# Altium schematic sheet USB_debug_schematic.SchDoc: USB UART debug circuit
size A3; Organization: Altium Limited; Address1: L3, 12a Rodborough Rd; Address2: Frenchs Forest; Address3: NSW; Address4: Australia 2086; DocumentNumber: 8; SheetNumber: 8; SheetTotal: 8
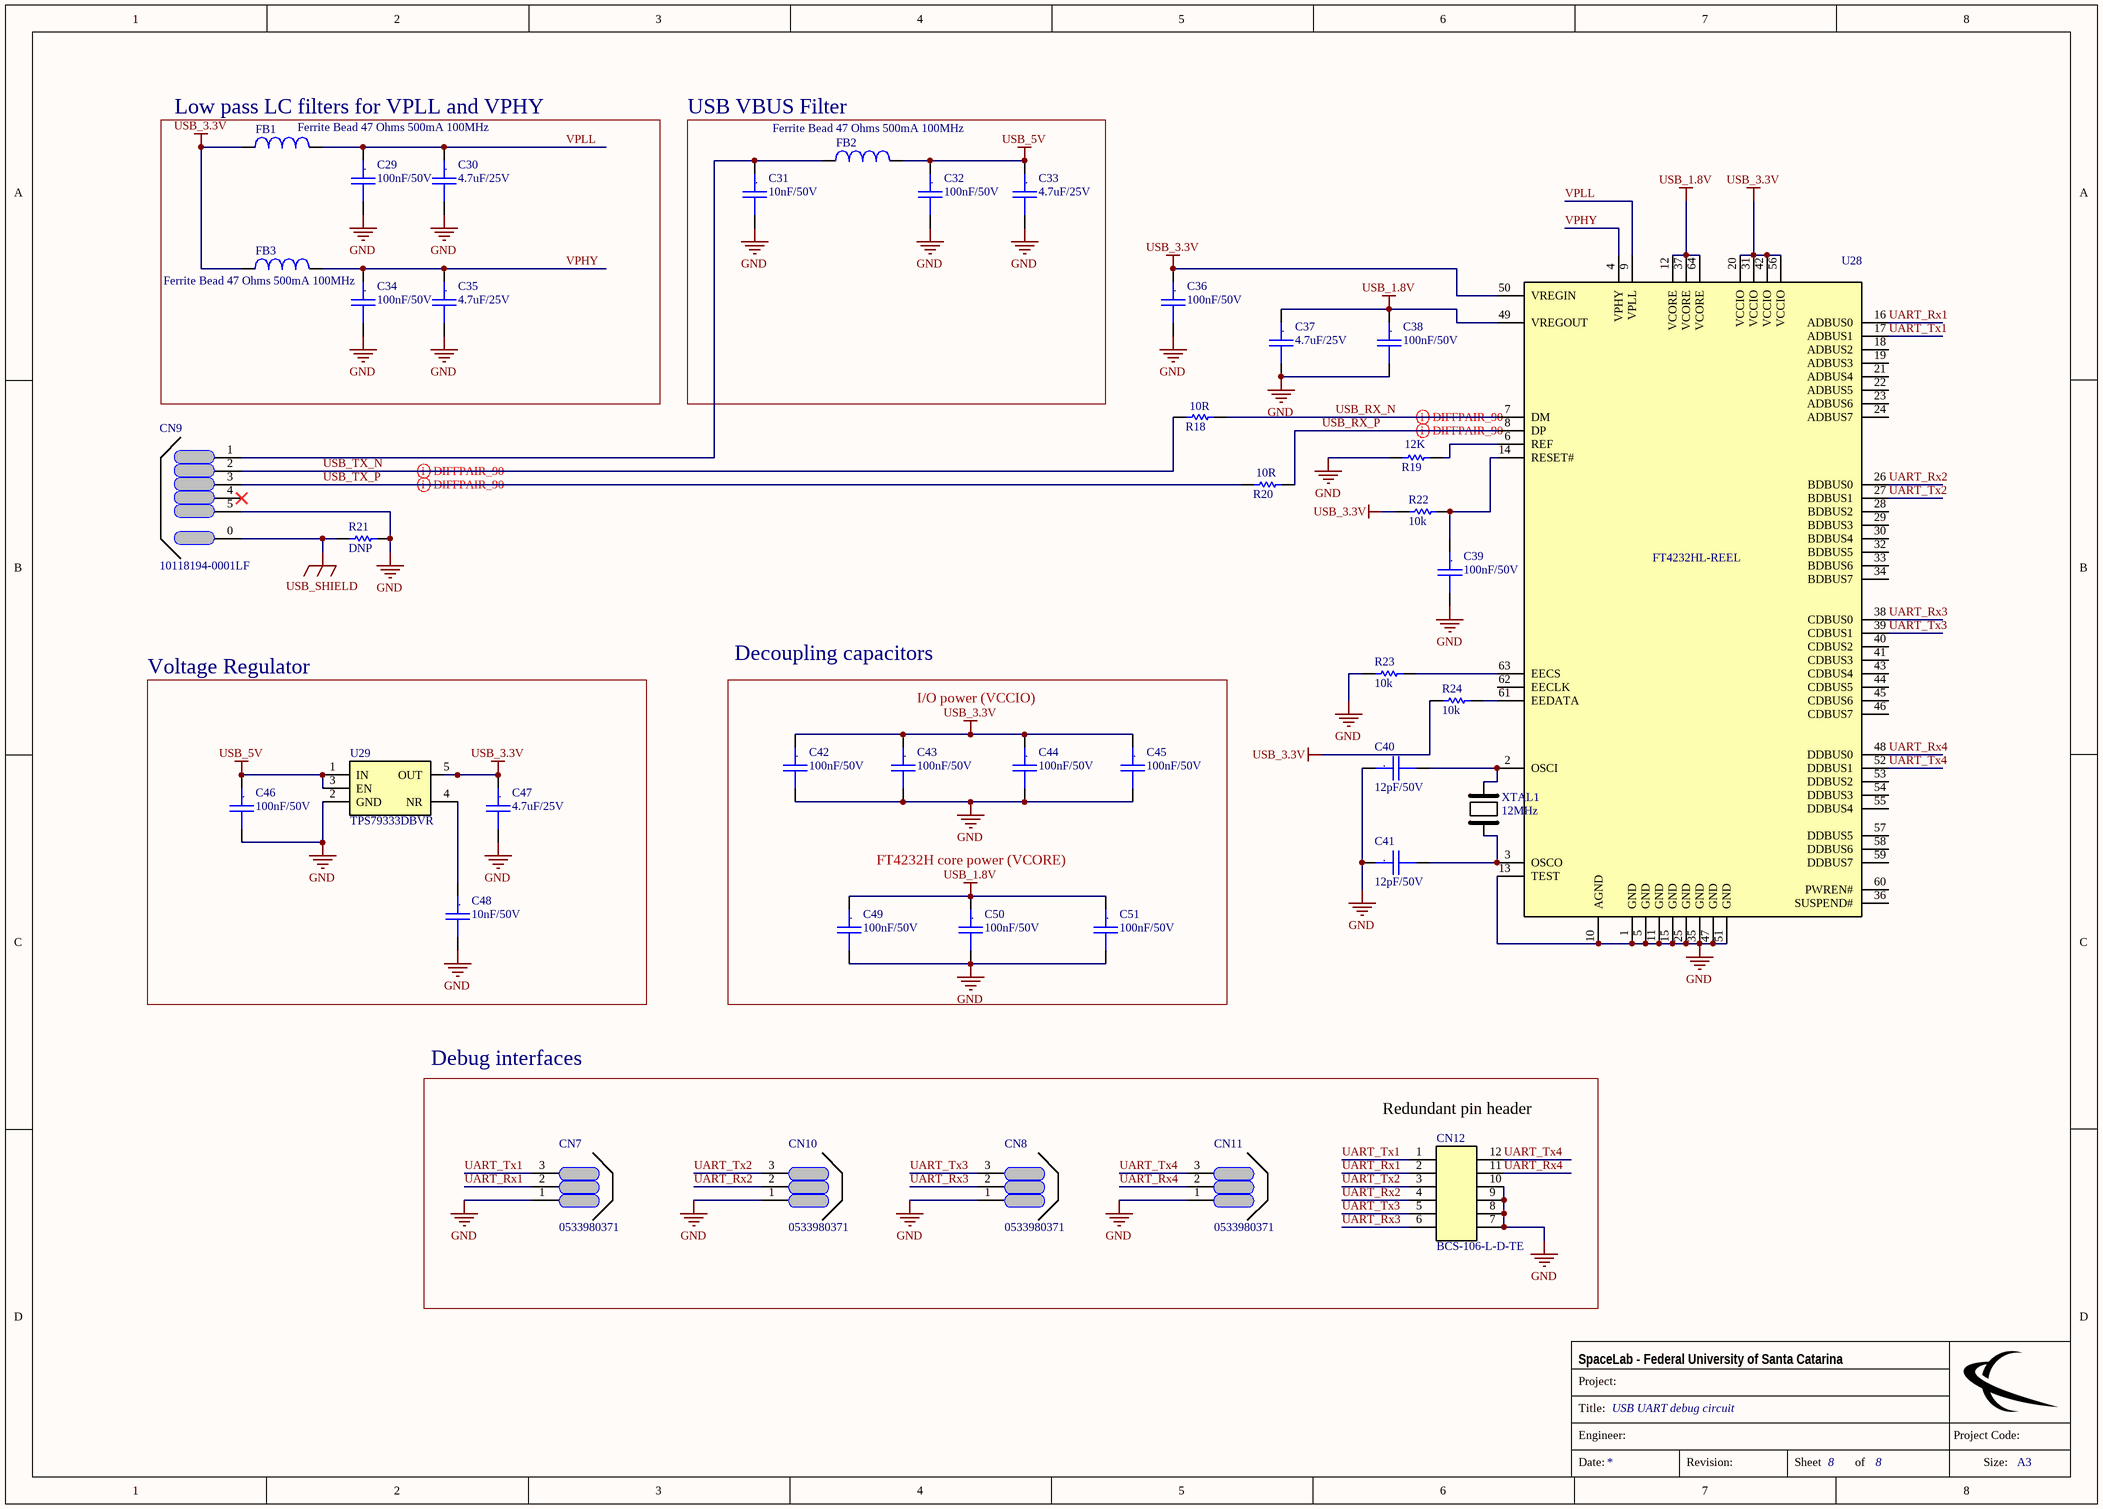
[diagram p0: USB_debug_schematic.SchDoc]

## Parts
C29  100nF/50V  [CC0603]
C30  4.7uF/25V  [CC0805]
C31  10nF/50V  [CC0805]
C32  100nF/50V  [CC0603]
C33  4.7uF/25V  [CC0805]
C34  100nF/50V  [CC0603]
C35  4.7uF/25V  [CC0805]
C36  100nF/50V  [CC0603]
C37  4.7uF/25V  [CC0805]
C38  100nF/50V  [CC0603]
C39  100nF/50V  [CC0603]
C40  12pF/50V  [CC0805]
C41  12pF/50V  [CC0805]
C42  100nF/50V  [CC0603]
C43  100nF/50V  [CC0603]
C44  100nF/50V  [CC0603]
C45  100nF/50V  [CC0603]
C46  100nF/50V  [CC0603]
C47  4.7uF/25V  [CC0805]
C48  10nF/50V  [CC0805]
C49  100nF/50V  [CC0603]
C50  100nF/50V  [CC0603]
C51  100nF/50V  [CC0603]
CN7  0533980371  [PICO BLADE 0533980371]
CN8  0533980371  [PICO BLADE 0533980371]
CN9  10118194-0001LF  [MICRO USB B 90GRAUS]
CN10  0533980371  [PICO BLADE 0533980371]
CN11  0533980371  [PICO BLADE 0533980371]
CN12  BCS-106-L-D-TE  [BCS-106-L-D-TE]
FB1  Ferrite Bead 47 Ohms 500mA 100MHz  [L0603]
FB2  Ferrite Bead 47 Ohms 500mA 100MHz  [L0603]
FB3  Ferrite Bead 47 Ohms 500mA 100MHz  [L0603]
R18  10R  [R0603_MD]
R19  12K  [R0805_MD]
R20  10R  [R0603_MD]
R21  DNP  [0805]
R22  10k  [0805]
R23  10k  [0805]
R24  10k  [0805]
U28  FT4232HL-REEL  [LQFP-64]
U29  TPS79333DBVR  [SOT23-5]
XTAL1  Frequency: 12MHz  [TXC 7A Series]  (hidden comment: 12.000MHz 12pF)

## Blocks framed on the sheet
Low pass LC filters for VPLL and VPHY: C29 C30 C34 C35 FB1 FB3
USB VBUS Filter: C31-C33 FB2
Voltage Regulator: C46-C48 U29
Decoupling capacitors: C42-C45 C49-C51
Debug interfaces: CN7 CN8 CN10-CN12

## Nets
GND: C29.2 C30.2 C31.2 C32.2 C33.2 C34.2 C35.2 C36.2 C37.2 C38.2 C39.2 C40.1 C41.1 C42.2 C43.2 C44.2 C45.2 C46.2 C47.2 C48.2 C49.2 C50.2 C51.2 CN7.1 CN8.1 CN9.5 CN10.1 CN11.1 CN12.7 CN12.8 CN12.9 CN12.10 R19.1 R21.1 R23.2 U28.1(GND) U28.5(GND) U28.10(AGND) U28.11(GND) U28.13(TEST) U28.15(GND) U28.25(GND) U28.35(GND) U28.47(GND) U28.51(GND) U29.2(GND)
USB_1.8V: C37.1 C38.1 C49.1 C50.1 C51.1 U28.12(VCORE) U28.37(VCORE) U28.49(VREGOUT) U28.64(VCORE)
USB_3.3V: C36.1 C42.1 C43.1 C44.1 C45.1 C47.1 FB1.1 FB3.1 R22.2 R24.2 U28.20(VCCIO) U28.31(VCCIO) U28.42(VCCIO) U28.50(VREGIN) U28.56(VCCIO) U29.5(OUT)
USB_5V: C32.1 C33.1 C46.1 FB2.2 U29.1(IN) U29.3(EN)
USB_SHIELD: CN9.0 R21.2
UART_Rx1: CN7.2 CN12.2 U28.16(ADBUS0)
UART_Rx2: CN10.2 CN12.4 U28.26(BDBUS0)
UART_Rx3: CN8.2 CN12.6 U28.38(CDBUS0)
UART_Rx4: CN11.2 CN12.11 U28.48(DDBUS0)
UART_Tx1: CN7.3 CN12.1 U28.17(ADBUS1)
UART_Tx2: CN10.3 CN12.3 U28.27(BDBUS1)
UART_Tx3: CN8.3 CN12.5 U28.39(CDBUS1)
UART_Tx4: CN11.3 CN12.12 U28.52(DDBUS1)
USB_RX_N: R18.2 U28.7(DM)
USB_RX_P: R20.2 U28.8(DP)
USB_TX_N: CN9.2 R18.1
USB_TX_P: CN9.3 R20.1
VPHY: C34.1 C35.1 FB3.2 U28.4(VPHY)
VPLL: C29.1 C30.1 FB1.2 U28.9(VPLL)
NetC31_1: C31.1 CN9.1 FB2.1
NetC39_1: C39.1 R22.1 U28.14(RESET#)
NetC40_2: C40.2 U28.2(OSCI) XTAL1.1
NetC41_2: C41.2 U28.3(OSCO) XTAL1.2
NetC48_1: C48.1 U29.4(NR)
NetR19_2: R19.2 U28.6(REF)
NetR23_1: R23.1 U28.63(EECS)
NetR24_1: R24.1 U28.61(EEDATA)

Not connected (* = marked no-connect by the designer): CN9 4*; U28 18(ADBUS2) 19(ADBUS3) 21(ADBUS4) 22(ADBUS5) 23(ADBUS6) 24(ADBUS7) 28(BDBUS2) 29(BDBUS3) 30(BDBUS4) 32(BDBUS5) 33(BDBUS6) 34(BDBUS7) 36(SUSPEND#) 40(CDBUS2) 41(CDBUS3) 43(CDBUS4) 44(CDBUS5) 45(CDBUS6) 46(CDBUS7) 53(DDBUS2) 54(DDBUS3) 55(DDBUS4) 57(DDBUS5) 58(DDBUS6) 59(DDBUS7) 60(PWREN#) 62(EECLK)

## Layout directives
differential pair: USB_RX_N, USB_RX_P, USB_TX_N, USB_TX_P

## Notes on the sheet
- I/O power (VCCIO)
- FT4232H core power (VCORE)
- (near CN12) Redundant pin header

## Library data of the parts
C29 C32 C34 C36 C38 C39 C42-C46 C49-C51 = Cap_Cer_X7R_100nF_50V_0603: CAP CER 100nF 50V 10% X7R 0603; Manufacturer Part Number: C0603C104K5RAC3121
C30 C33 C35 C37 C47 = Cap_Cer_X7R_4.7uF_25V_0805: CAP CER 4.7uF 25V 10% X7R 0805; Manufacturer Part Number: C0805C475K3RACAUTO
C31 C48 = Cap_Cer_X7R_10nF_50V_0805: CAP CER 0.01uF 50V 10% X7R 0805; Manufacturer Part Number: 08055C103KAT4A
C40 C41 = Cap_Cer_X7R_12pF_50V_0805: CAP CER 12pF 50V 1% C0G/NP0 0805; Manufacturer Part Number: CL21C120FBANNNC
CN7 CN8 CN10 CN11 = 0533980371: CONN HEADER SMD 3POS 1.25MM; Manufacturer: Molex; Manufacturer Part Number: 53398-0371; N of Positions: 3
CN9 = 10118194-0001LF: CONN USB MICRO B RECPT SMT R/A; Manufacturer: FCI; N of Positions: 5; Pitch: 0.65mm
CN12 = BCS-106-L-D-TE: CONN RCPT 12POS 0.1 GOLD PCB; Manufacturer: Samtec; Number of Contacts: 12; Gender: Receptacle; Max Current Rating: 5.9A; Contact Resistance: 10mR; Max Voltage Rating (AC): 475V; Pitch: 2.54mm; Row Spacing: 0.1inch
FB1-FB3 = 742792608: WURTH ELEKTRONIK   742792608   FERRITE BEAD, 47 OHM, 0.5A, 0603; Manufacturer: Wurth Electronics; Resistance: 100mR; Inductance: 1H; Tolerance: 25%; Number of Lines: 1
R18 R20 = RC0603FR-0710RL: RES 10R OHM 1/10W 1% 0603; Manufacturer: Yageo; Temperature Coefficient: 200ppm/°C; Voltage Rating (DC): 50V; Power Rating: 100mW
R19 = RMCF0805FT12K0: RES 12K OHM 1/8W 1% 0805; Manufacturer: Stackpole Electronics; Power Rating: 125mW; Temperature Coefficient: 100ppm/°C
R21 = RDNP_0805: RES DNP 0805; Manufacturer Part Number: CRCW08050000Z0EA
R22-R24 = R10k_1%_1/8W_0805: RES 10K OHM 1/8W 1%  0805; Manufacturer Part Number: CRCW080510K0FKEA
U28 = FT4232HL-REEL: FTDI - FT4232HL-REEL - USB-UART/MPSSE, 4232, QUAD, 64LQFP; Number of Channels: 1; Data Rate: 480Mbps; Operating Supply Voltage: 3.3V; Max Supply Voltage: 3.63V; Min Supply Voltage: 1.62V; Operating Supply Current: 70mA; Number of Transceivers: 4; ESD Protection: Yes; Interface: UART
U29 = TPS79333DBVR: TEXAS INSTRUMENTS - TPS79333DBVR - IC, V REG, LINEAR, 0.2A, SOT-23-5; Number of Outputs: 1; Output Voltage: 3.3V; Max Power Dissipation: 560mW; Max Output Current: 200mA; Max Input Voltage: 5.5V; Min Input Voltage: 2.7V; Polarity: Positive; Quiescent Current: 200uA; Accuracy: 2%; Output Type: Fixed; Dropout Voltage: 102mV; Min Current Limit: 285mA; Input Bias Current: 170uA
XTAL1 = AA-12.000MAGE-T: Crystals 12.000MHz 30ppm 12pF -40C to 85C; Manufacturer: TXC; ESR (Equivalent Series Resistance): 100R; Frequency Stability: 50ppm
